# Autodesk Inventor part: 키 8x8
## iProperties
Company: 한국ATC센터
Created: 2014-10
Part Number: 키 8x8
Document SubType Name: Modeling
Designer: 한국ATC센터
Density: 7.86 g/cm^3
Material: 강, 연강
Mass: 10.2483 g
Surface Area: 7.8646 cm^2
Volume: 1.30386 cm^3
Author: KYOUNG IL JANG
Revision Number: 1
